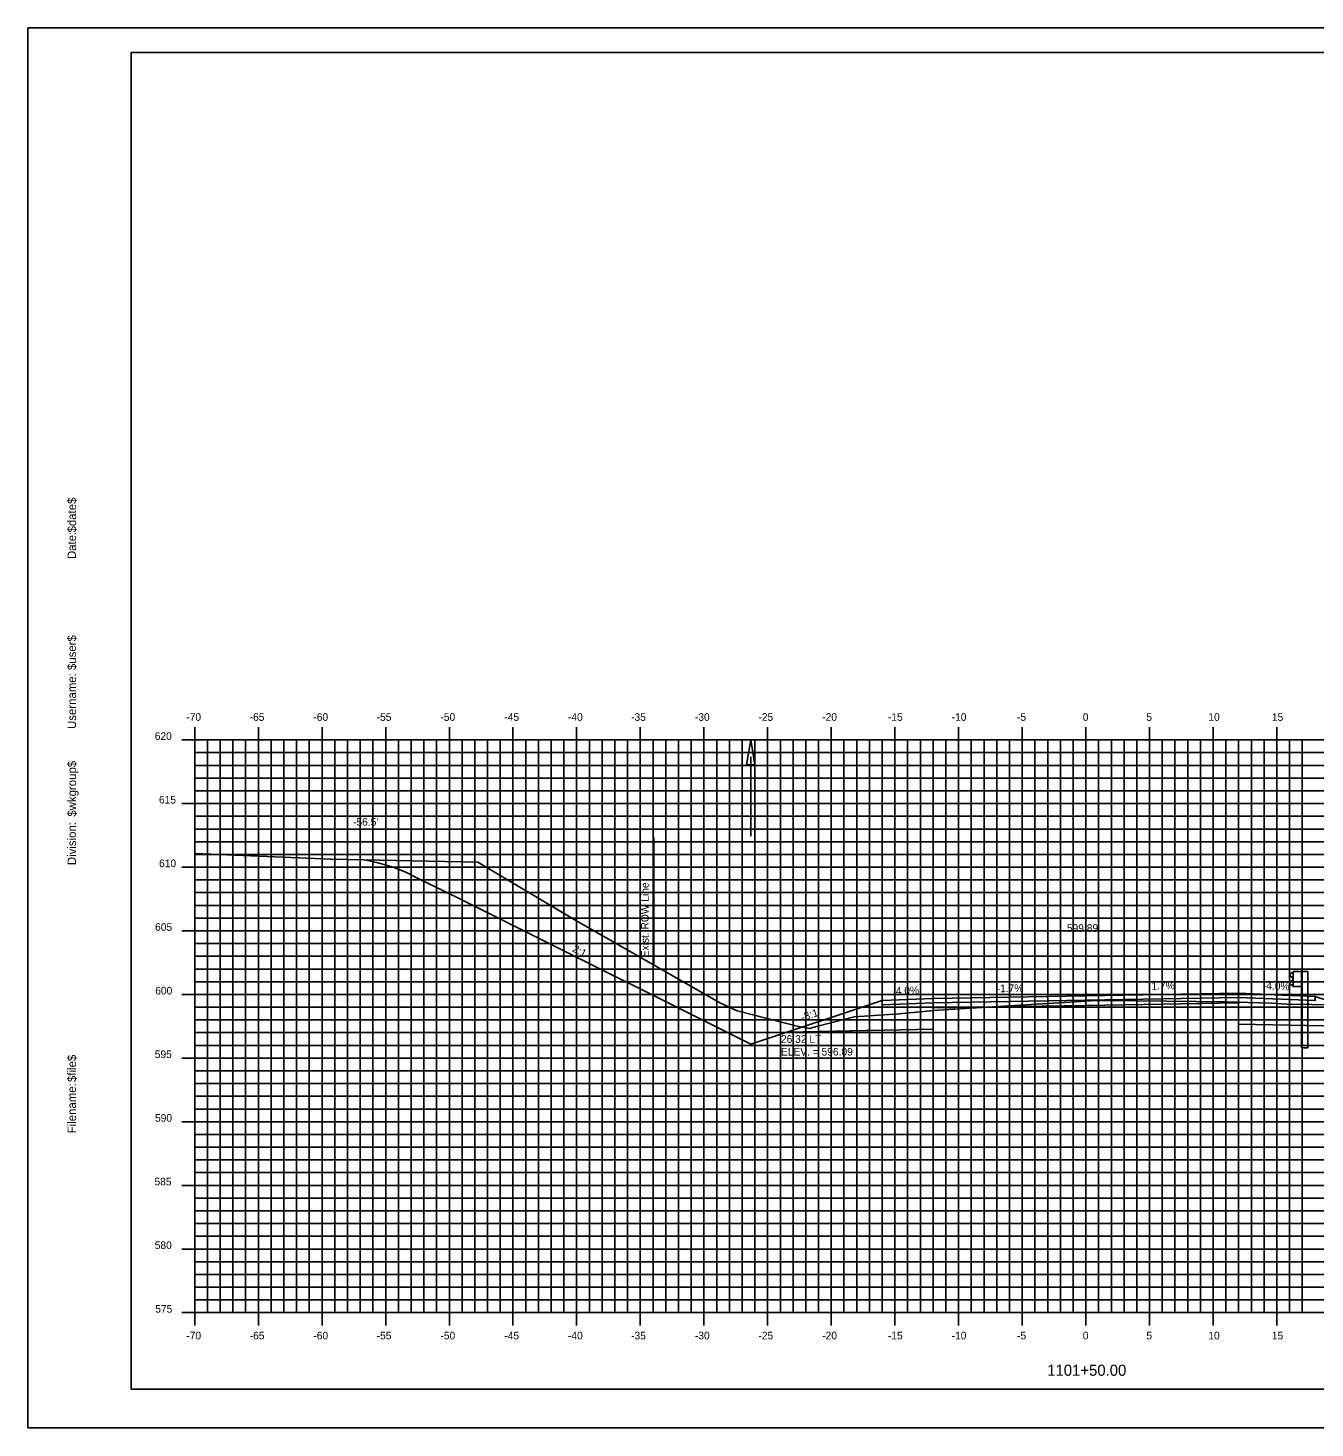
# Model space of a CAD drawing. Extents: x 1076747 to 1076917, y 779716 to 779826.
# Drawn here: x 1076747.2 to 1076848.3, y 779715.6 to 779825.6 of the extents above; entities that cross this region are included whole.
import ezdxf

# ---------------------------------------------------------------- set-up
doc = ezdxf.new("R2010")
doc.units = 0
for name, color, linetype in [('ANNOTATION', 7, 'Continuous'), ('BORDER', 7, 'Continuous'), ('D_Drainage_Culvert', 7, 'Continuous'), ('D_Drainage_Ditch_Line', 7, 'Continuous'), ('D_Guardrail_Beam_Rt', 7, 'Continuous'), ('D_Roadway_Centerline', 7, 'Continuous'), ('D_Roadway_Centerline_Text', 7, 'Continuous'), ('D_Roadway_Drive_SubGrade', 7, 'Continuous'), ('D_Roadway_Edge_Pavement', 7, 'Continuous'), ('D_Roadway_Edge_Shoulder', 7, 'Continuous'), ('D_Roadway_Pavement', 7, 'Continuous'), ('D_Roadway_SubGrade', 7, 'Continuous'), ('D_Text_Standard', 7, 'Continuous'), ('E_ROW_Line', 7, 'Continuous'), ('H_V ANNOTATION', 7, 'Continuous'), ('MAJOR', 7, 'Continuous'), ('MINOR', 7, 'Continuous'), ('PLOT BOUNDARY', 7, 'Continuous'), ('S_Roadway_Centerline', 7, 'Continuous')]:
    doc.layers.add(name, color=color, linetype=linetype)

msp = doc.modelspace()

# ---------------------------------------------------------------- linework, layer by layer
at = {"layer": 'BORDER'}
msp.add_lwpolyline([(1076755.31, 779718.71), (1076915.31, 779718.71), (1076915.31, 779823.71), (1076755.31, 779823.71)], close=True, dxfattribs=at)
at = {"layer": 'D_Drainage_Culvert'}
msp.add_line((1076814.31, 779746.9), (1076806.85, 779746.75), dxfattribs=at)
at = {"layer": 'D_Drainage_Ditch_Line'}
msp.add_line((1076803.98, 779768.39), (1076803.98, 779762.15), dxfattribs=at)
msp.add_lwpolyline([(1076804.31, 779767.74), (1076803.65, 779767.74), (1076803.98, 779769.71)], close=True, dxfattribs=at)
at = {"layer": 'D_Guardrail_Beam_Rt'}
for points in [[(1076846.59, 779751.51), (1076847.25, 779751.51), (1076847.25, 779750.33), (1076846.59, 779750.33)], [(1076847.25, 779751.51), (1076847.74, 779751.51), (1076847.74, 779745.51), (1076847.25, 779745.51)]]:
    msp.add_lwpolyline(points, close=True, dxfattribs=at)
msp.add_lwpolyline([(1076846.59, 779751.43), (1076846.5, 779751.42), (1076846.49, 779751.41), (1076846.34, 779751.31), (1076846.34, 779751.17), (1076846.54, 779751.03), (1076846.57, 779750.97), (1076846.57, 779750.88), (1076846.54, 779750.81), (1076846.34, 779750.68), (1076846.34, 779750.53), (1076846.49, 779750.43), (1076846.5, 779750.43), (1076846.59, 779750.41)], dxfattribs=at)
at = {"layer": 'D_Roadway_Centerline'}
msp.add_lwpolyline([(1076773.81, 779760.27), (1076774.81, 779760.02), (1076775.89, 779759.7), (1076776.89, 779759.31), (1076777.81, 779758.84), (1076781.14, 779757.22), (1076784.39, 779755.59)], dxfattribs=at)
at = {"layer": 'D_Roadway_Drive_SubGrade'}
msp.add_lwpolyline([(1076814.31, 779749.24), (1076803.98, 779745.8), (1076784.39, 779755.59)], dxfattribs=at)
at = {"layer": 'D_Roadway_Edge_Pavement'}
msp.add_lwpolyline([(1076818.31, 779749.06), (1076818.31, 779749.4), (1076830.31, 779749.6), (1076842.31, 779749.8), (1076842.31, 779749.47), (1076830.31, 779749.26)], close=True, dxfattribs=at)
at = {"layer": 'D_Roadway_Edge_Shoulder'}
msp.add_line((1076842.31, 779749.8), (1076848.31, 779749.56), dxfattribs=at)
msp.add_lwpolyline([(1076818.31, 779749.4), (1076814.31, 779749.24), (1076814.31, 779748.9), (1076818.31, 779749.06)], close=True, dxfattribs=at)
msp.add_lwpolyline([(1076842.31, 779749.8), (1076846.31, 779749.64), (1076846.31, 779749.64)], dxfattribs=at)
at = {"layer": 'D_Roadway_Pavement'}
msp.add_lwpolyline([(1076818.31, 779748.65), (1076818.31, 779749.06), (1076830.31, 779749.26), (1076842.31, 779749.47), (1076842.31, 779749.05), (1076830.31, 779748.85)], close=True, dxfattribs=at)
msp.add_lwpolyline([(1076818.31, 779749.06), (1076818.31, 779748.65)], dxfattribs=at)
msp.add_lwpolyline([(1076818.31, 779749.06), (1076818.31, 779748.65)], dxfattribs=at)
at = {"layer": 'D_Roadway_SubGrade'}
msp.add_lwpolyline([(1076842.31, 779747.38), (1076842.31, 779747.97), (1076842.31, 779749.47), (1076842.31, 779749.47), (1076848.31, 779749.23), (1076848.31, 779749.56), (1076855.64, 779747.12)], close=True, dxfattribs=at)
msp.add_lwpolyline([(1076806.85, 779746.75), (1076818.31, 779746.98), (1076818.31, 779749.06), (1076814.31, 779748.9), (1076814.31, 779749.24)], dxfattribs=at)
at = {"layer": 'E_ROW_Line'}
msp.add_line((1076796.37, 779752.03), (1076796.37, 779762.03), dxfattribs=at)
msp.add_line((1076796.37, 779752.03), (1076796.37, 779762.03), dxfattribs=at)
at = {"layer": 'MAJOR'}
for p, q in [((1076760.31, 779770.71), (1076760.31, 779769.71)), ((1076765.31, 779770.71), (1076765.31, 779769.71)), ((1076770.31, 779770.71), (1076770.31, 779769.71)), ((1076775.31, 779770.71), (1076775.31, 779769.71)), ((1076780.31, 779770.71), (1076780.31, 779769.71)), ((1076785.31, 779770.71), (1076785.31, 779769.71)), ((1076790.31, 779770.71), (1076790.31, 779769.71)), ((1076795.31, 779770.71), (1076795.31, 779769.71)), ((1076800.31, 779770.71), (1076800.31, 779769.71)), ((1076805.31, 779770.71), (1076805.31, 779769.71)), ((1076810.31, 779770.71), (1076810.31, 779769.71)), ((1076815.31, 779770.71), (1076815.31, 779769.71)), ((1076820.31, 779770.71), (1076820.31, 779769.71)), ((1076825.31, 779770.71), (1076825.31, 779769.71)), ((1076830.31, 779770.71), (1076830.31, 779769.71)), ((1076835.31, 779770.71), (1076835.31, 779769.71)), ((1076840.31, 779770.71), (1076840.31, 779769.71)), ((1076845.31, 779770.71), (1076845.31, 779769.71)), ((1076759.31, 779769.71), (1076760.31, 779769.71)), ((1076760.31, 779769.71), (1076900.31, 779769.71)), ((1076760.31, 779724.71), (1076760.31, 779769.71)), ((1076760.31, 779724.71), (1076760.31, 779769.71)), ((1076760.31, 779769.71), (1076900.31, 779769.71)), ((1076765.31, 779724.71), (1076765.31, 779769.71)), ((1076770.31, 779724.71), (1076770.31, 779769.71)), ((1076775.31, 779724.71), (1076775.31, 779769.71)), ((1076780.31, 779724.71), (1076780.31, 779769.71)), ((1076785.31, 779724.71), (1076785.31, 779769.71)), ((1076790.31, 779724.71), (1076790.31, 779769.71)), ((1076795.31, 779724.71), (1076795.31, 779769.71)), ((1076800.31, 779724.71), (1076800.31, 779769.71)), ((1076805.31, 779724.71), (1076805.31, 779769.71)), ((1076810.31, 779724.71), (1076810.31, 779769.71)), ((1076815.31, 779724.71), (1076815.31, 779769.71)), ((1076820.31, 779724.71), (1076820.31, 779769.71)), ((1076825.31, 779724.71), (1076825.31, 779769.71)), ((1076830.31, 779724.71), (1076830.31, 779769.71)), ((1076835.31, 779724.71), (1076835.31, 779769.71)), ((1076840.31, 779724.71), (1076840.31, 779769.71)), ((1076845.31, 779724.71), (1076845.31, 779769.71)), ((1076759.31, 779764.71), (1076760.31, 779764.71)), ((1076760.31, 779764.71), (1076900.31, 779764.71)), ((1076759.31, 779759.71), (1076760.31, 779759.71)), ((1076760.31, 779759.71), (1076900.31, 779759.71)), ((1076759.31, 779754.71), (1076760.31, 779754.71)), ((1076760.31, 779754.71), (1076900.31, 779754.71)), ((1076759.31, 779749.71), (1076760.31, 779749.71)), ((1076760.31, 779749.71), (1076900.31, 779749.71)), ((1076759.31, 779744.71), (1076760.31, 779744.71)), ((1076760.31, 779744.71), (1076900.31, 779744.71)), ((1076759.31, 779739.71), (1076760.31, 779739.71)), ((1076760.31, 779739.71), (1076900.31, 779739.71)), ((1076759.31, 779734.71), (1076760.31, 779734.71)), ((1076760.31, 779734.71), (1076900.31, 779734.71)), ((1076759.31, 779729.71), (1076760.31, 779729.71)), ((1076760.31, 779729.71), (1076900.31, 779729.71)), ((1076759.31, 779724.71), (1076760.31, 779724.71)), ((1076760.31, 779724.71), (1076900.31, 779724.71)), ((1076760.31, 779724.71), (1076900.31, 779724.71)), ((1076760.31, 779723.7), (1076760.31, 779724.71)), ((1076765.31, 779723.7), (1076765.31, 779724.71)), ((1076770.31, 779723.7), (1076770.31, 779724.71)), ((1076775.31, 779723.7), (1076775.31, 779724.71)), ((1076780.31, 779723.7), (1076780.31, 779724.71)), ((1076785.31, 779723.7), (1076785.31, 779724.71)), ((1076790.31, 779723.7), (1076790.31, 779724.71)), ((1076795.31, 779723.7), (1076795.31, 779724.71)), ((1076800.31, 779723.7), (1076800.31, 779724.71)), ((1076805.31, 779723.7), (1076805.31, 779724.71)), ((1076810.31, 779723.7), (1076810.31, 779724.71)), ((1076815.31, 779723.7), (1076815.31, 779724.71)), ((1076820.31, 779723.7), (1076820.31, 779724.71)), ((1076825.31, 779723.7), (1076825.31, 779724.71)), ((1076830.31, 779723.7), (1076830.31, 779724.71)), ((1076835.31, 779723.7), (1076835.31, 779724.71)), ((1076840.31, 779723.7), (1076840.31, 779724.71)), ((1076845.31, 779723.7), (1076845.31, 779724.71))]:
    msp.add_line(p, q, dxfattribs=at)
at = {"layer": 'MINOR'}
for p, q in [((1076761.31, 779724.71), (1076761.31, 779769.71)), ((1076762.31, 779724.71), (1076762.31, 779769.71)), ((1076763.31, 779724.71), (1076763.31, 779769.71)), ((1076764.31, 779724.71), (1076764.31, 779769.71)), ((1076766.31, 779724.71), (1076766.31, 779769.71)), ((1076767.31, 779724.71), (1076767.31, 779769.71)), ((1076768.31, 779724.71), (1076768.31, 779769.71)), ((1076769.31, 779724.71), (1076769.31, 779769.71)), ((1076771.31, 779724.71), (1076771.31, 779769.71)), ((1076772.31, 779724.71), (1076772.31, 779769.71)), ((1076773.31, 779724.71), (1076773.31, 779769.71)), ((1076774.31, 779724.71), (1076774.31, 779769.71)), ((1076776.31, 779724.71), (1076776.31, 779769.71)), ((1076777.31, 779724.71), (1076777.31, 779769.71)), ((1076778.31, 779724.71), (1076778.31, 779769.71)), ((1076779.31, 779724.71), (1076779.31, 779769.71)), ((1076781.31, 779724.71), (1076781.31, 779769.71)), ((1076782.31, 779724.71), (1076782.31, 779769.71)), ((1076783.31, 779724.71), (1076783.31, 779769.71)), ((1076784.31, 779724.71), (1076784.31, 779769.71)), ((1076786.31, 779724.71), (1076786.31, 779769.71)), ((1076787.31, 779724.71), (1076787.31, 779769.71)), ((1076788.31, 779724.71), (1076788.31, 779769.71)), ((1076789.31, 779724.71), (1076789.31, 779769.71)), ((1076791.31, 779724.71), (1076791.31, 779769.71)), ((1076792.31, 779724.71), (1076792.31, 779769.71)), ((1076793.31, 779724.71), (1076793.31, 779769.71)), ((1076794.31, 779724.71), (1076794.31, 779769.71)), ((1076796.31, 779724.71), (1076796.31, 779769.71)), ((1076797.31, 779724.71), (1076797.31, 779769.71)), ((1076798.31, 779724.71), (1076798.31, 779769.71)), ((1076799.31, 779724.71), (1076799.31, 779769.71)), ((1076801.31, 779724.71), (1076801.31, 779769.71)), ((1076802.31, 779724.71), (1076802.31, 779769.71)), ((1076803.31, 779724.71), (1076803.31, 779769.71)), ((1076804.31, 779724.71), (1076804.31, 779769.71)), ((1076806.31, 779724.71), (1076806.31, 779769.71)), ((1076807.31, 779724.71), (1076807.31, 779769.71)), ((1076808.31, 779724.71), (1076808.31, 779769.71)), ((1076809.31, 779724.71), (1076809.31, 779769.71)), ((1076811.31, 779724.71), (1076811.31, 779769.71)), ((1076812.31, 779724.71), (1076812.31, 779769.71)), ((1076813.31, 779724.71), (1076813.31, 779769.71)), ((1076814.31, 779724.71), (1076814.31, 779769.71)), ((1076816.31, 779724.71), (1076816.31, 779769.71)), ((1076817.31, 779724.71), (1076817.31, 779769.71)), ((1076818.31, 779724.71), (1076818.31, 779769.71)), ((1076819.31, 779724.71), (1076819.31, 779769.71)), ((1076821.31, 779724.71), (1076821.31, 779769.71)), ((1076822.31, 779724.71), (1076822.31, 779769.71)), ((1076823.31, 779724.71), (1076823.31, 779769.71)), ((1076824.31, 779724.71), (1076824.31, 779769.71)), ((1076826.31, 779724.71), (1076826.31, 779769.71)), ((1076827.31, 779724.71), (1076827.31, 779769.71)), ((1076828.31, 779724.71), (1076828.31, 779769.71)), ((1076829.31, 779724.71), (1076829.31, 779769.71)), ((1076831.31, 779724.71), (1076831.31, 779769.71)), ((1076832.31, 779724.71), (1076832.31, 779769.71)), ((1076833.31, 779724.71), (1076833.31, 779769.71)), ((1076834.31, 779724.71), (1076834.31, 779769.71)), ((1076836.31, 779724.71), (1076836.31, 779769.71)), ((1076837.31, 779724.71), (1076837.31, 779769.71)), ((1076838.31, 779724.71), (1076838.31, 779769.71)), ((1076839.31, 779724.71), (1076839.31, 779769.71)), ((1076841.31, 779724.71), (1076841.31, 779769.71)), ((1076842.31, 779724.71), (1076842.31, 779769.71)), ((1076843.31, 779724.71), (1076843.31, 779769.71)), ((1076844.31, 779724.71), (1076844.31, 779769.71)), ((1076846.31, 779724.71), (1076846.31, 779769.71)), ((1076847.31, 779724.71), (1076847.31, 779769.71)), ((1076760.31, 779768.71), (1076900.31, 779768.71)), ((1076760.31, 779768.71), (1076761.31, 779768.71)), ((1076760.31, 779767.71), (1076900.31, 779767.71)), ((1076760.31, 779767.71), (1076761.31, 779767.71)), ((1076760.31, 779766.71), (1076900.31, 779766.71)), ((1076760.31, 779766.71), (1076761.31, 779766.71)), ((1076760.31, 779765.71), (1076900.31, 779765.71)), ((1076760.31, 779765.71), (1076761.31, 779765.71)), ((1076760.31, 779763.71), (1076900.31, 779763.71)), ((1076760.31, 779763.71), (1076761.31, 779763.71)), ((1076760.31, 779762.71), (1076900.31, 779762.71)), ((1076760.31, 779762.71), (1076761.31, 779762.71)), ((1076760.31, 779761.71), (1076900.31, 779761.71)), ((1076760.31, 779761.71), (1076761.31, 779761.71)), ((1076760.31, 779760.71), (1076900.31, 779760.71)), ((1076760.31, 779760.71), (1076761.31, 779760.71)), ((1076760.31, 779758.71), (1076900.31, 779758.71)), ((1076760.31, 779758.71), (1076761.31, 779758.71)), ((1076760.31, 779757.71), (1076900.31, 779757.71)), ((1076760.31, 779757.71), (1076761.31, 779757.71)), ((1076760.31, 779756.71), (1076900.31, 779756.71)), ((1076760.31, 779756.71), (1076761.31, 779756.71)), ((1076760.31, 779755.71), (1076900.31, 779755.71)), ((1076760.31, 779755.71), (1076761.31, 779755.71)), ((1076760.31, 779753.71), (1076900.31, 779753.71)), ((1076760.31, 779753.71), (1076761.31, 779753.71)), ((1076760.31, 779752.71), (1076900.31, 779752.71)), ((1076760.31, 779752.71), (1076761.31, 779752.71)), ((1076760.31, 779751.71), (1076900.31, 779751.71)), ((1076760.31, 779751.71), (1076761.31, 779751.71)), ((1076760.31, 779750.71), (1076900.31, 779750.71)), ((1076760.31, 779750.71), (1076761.31, 779750.71)), ((1076760.31, 779748.71), (1076900.31, 779748.71)), ((1076760.31, 779748.71), (1076761.31, 779748.71)), ((1076760.31, 779747.71), (1076900.31, 779747.71)), ((1076760.31, 779747.71), (1076761.31, 779747.71)), ((1076760.31, 779746.71), (1076900.31, 779746.71)), ((1076760.31, 779746.71), (1076761.31, 779746.71)), ((1076760.31, 779745.71), (1076900.31, 779745.71)), ((1076760.31, 779745.71), (1076761.31, 779745.71)), ((1076760.31, 779743.71), (1076900.31, 779743.71)), ((1076760.31, 779743.71), (1076761.31, 779743.71)), ((1076760.31, 779742.71), (1076900.31, 779742.71)), ((1076760.31, 779742.71), (1076761.31, 779742.71)), ((1076760.31, 779741.71), (1076900.31, 779741.71)), ((1076760.31, 779741.71), (1076761.31, 779741.71)), ((1076760.31, 779740.71), (1076900.31, 779740.71)), ((1076760.31, 779740.71), (1076761.31, 779740.71)), ((1076760.31, 779738.71), (1076900.31, 779738.71)), ((1076760.31, 779738.71), (1076761.31, 779738.71)), ((1076760.31, 779737.71), (1076900.31, 779737.71)), ((1076760.31, 779737.71), (1076761.31, 779737.71)), ((1076760.31, 779736.71), (1076900.31, 779736.71)), ((1076760.31, 779736.71), (1076761.31, 779736.71)), ((1076760.31, 779735.71), (1076900.31, 779735.71)), ((1076760.31, 779735.71), (1076761.31, 779735.71)), ((1076760.31, 779733.71), (1076900.31, 779733.71)), ((1076760.31, 779733.71), (1076761.31, 779733.71)), ((1076760.31, 779732.71), (1076900.31, 779732.71)), ((1076760.31, 779732.71), (1076761.31, 779732.71)), ((1076760.31, 779731.71), (1076900.31, 779731.71)), ((1076760.31, 779731.71), (1076761.31, 779731.71)), ((1076760.31, 779730.71), (1076900.31, 779730.71)), ((1076760.31, 779730.71), (1076761.31, 779730.71)), ((1076760.31, 779728.71), (1076900.31, 779728.71)), ((1076760.31, 779728.71), (1076761.31, 779728.71)), ((1076760.31, 779727.71), (1076900.31, 779727.71)), ((1076760.31, 779727.71), (1076761.31, 779727.71)), ((1076760.31, 779726.71), (1076900.31, 779726.71)), ((1076760.31, 779726.71), (1076761.31, 779726.71)), ((1076760.31, 779725.71), (1076900.31, 779725.71)), ((1076760.31, 779725.71), (1076761.31, 779725.71))]:
    msp.add_line(p, q, dxfattribs=at)
at = {"layer": 'PLOT BOUNDARY'}
msp.add_lwpolyline([(1076747.21, 779715.65), (1076917.21, 779715.65), (1076917.21, 779825.65), (1076747.21, 779825.65)], close=True, dxfattribs=at)
at = {"layer": 'S_Roadway_Centerline'}
msp.add_lwpolyline([(1076760.31, 779760.79), (1076770.99, 779760.33), (1076782.56, 779760.11), (1076790.11, 779755.6), (1076801.62, 779749.03), (1076802.91, 779748.43), (1076804.35, 779748.05), (1076807.74, 779747.19), (1076808.6, 779747.03), (1076809.25, 779747.21), (1076812.11, 779747.94), (1076815.62, 779748.18), (1076818.68, 779748.47), (1076830.35, 779749.18), (1076830.94, 779749.23), (1076832.05, 779749.23), (1076841.27, 779749.14), (1076844.85, 779749.02), (1076846.55, 779748.91), (1076847, 779748.94), (1076849.09, 779748.9)], dxfattribs=at)

# ---------------------------------------------------------------- texts
at = {"layer": 'ANNOTATION'}
for s, rotation, p in [('2:1', 333.4349, (1076789.91, 779753.11)), ('-1.7%', 0.9596, (1076823.31, 779749.88)), ('1.7%', 0.9596, (1076835.47, 779750.08)), ('-4.0%', 357.7094, (1076844.2, 779750.12)), ('-4.0%', 2.2906, (1076815.12, 779749.67)), ('-3:1', 18.4349, (1076808.03, 779747.6))]:
    msp.add_text(s, height=0.6, rotation=rotation, dxfattribs=at).set_placement(p)
for s, p in [('26.32 LT', (1076806.36, 779745.91)), ('ELEV. = 596.09', (1076806.36, 779744.91))]:
    msp.add_text(s, height=0.6, dxfattribs=at).set_placement(p)
at = {"layer": 'BORDER'}
for s, p in [('$date$', (1076750.99, 779786.01)), ('Date:', (1076750.99, 779783.92)), ('$user$', (1076750.99, 779775.2)), ('Username:', (1076750.99, 779770.57)), ('$wkgroup$', (1076750.99, 779763.68)), ('Division:', (1076750.99, 779759.87)), ('$file$', (1076750.99, 779742.83)), ('Filename:', (1076750.99, 779738.8))]:
    msp.add_text(s, height=0.67, rotation=90, dxfattribs=at).set_placement(p)
at = {"layer": 'D_Roadway_Centerline_Text'}
msp.add_text('599.89', height=0.6, dxfattribs=at).set_placement((1076828.82, 779754.63))
at = {"layer": 'D_Text_Standard'}
msp.add_text("-56.5'", height=0.6, dxfattribs=at).set_placement((1076772.75, 779762.97))
at = {"layer": 'E_ROW_Line'}
msp.add_text('Exist. ROW Line', height=0.6, rotation=90, dxfattribs=at).set_placement((1076795.97, 779752.63))
at = {"layer": 'H_V ANNOTATION'}
for s, height, p in [('-70', 0.6, (1076759.65, 779771.21)), ('-65', 0.6, (1076764.63, 779771.21)), ('-60', 0.6, (1076769.63, 779771.21)), ('-55', 0.6, (1076774.6, 779771.21)), ('-50', 0.6, (1076779.61, 779771.21)), ('-45', 0.6, (1076784.63, 779771.21)), ('-40', 0.6, (1076789.63, 779771.21)), ('-35', 0.6, (1076794.59, 779771.21)), ('-30', 0.6, (1076799.6, 779771.21)), ('-25', 0.6, (1076804.59, 779771.21)), ('-20', 0.6, (1076809.6, 779771.21)), ('-15', 0.6, (1076814.76, 779771.21)), ('-10', 0.6, (1076819.77, 779771.21)), ('-5', 0.6, (1076824.9, 779771.21)), ('0', 0.6, (1076830.07, 779771.21)), ('5', 0.6, (1076835.06, 779771.21)), ('10', 0.6, (1076839.93, 779771.21)), ('15', 0.6, (1076844.92, 779771.21)), ('620', 0.6, (1076757.17, 779769.71)), ('615', 0.6, (1076757.5, 779764.71)), ('610', 0.6, (1076757.51, 779759.71)), ('605', 0.6, (1076757.2, 779754.71)), ('600', 0.6, (1076757.21, 779749.71)), ('595', 0.6, (1076757.17, 779744.71)), ('590', 0.6, (1076757.19, 779739.71)), ('585', 0.6, (1076757.15, 779734.71)), ('580', 0.6, (1076757.17, 779729.71)), ('575', 0.6, (1076757.21, 779724.71)), ('-70', 0.6, (1076759.65, 779722.61)), ('-65', 0.6, (1076764.63, 779722.61)), ('-60', 0.6, (1076769.63, 779722.61)), ('-55', 0.6, (1076774.6, 779722.61)), ('-50', 0.6, (1076779.61, 779722.61)), ('-45', 0.6, (1076784.63, 779722.61)), ('-40', 0.6, (1076789.63, 779722.61)), ('-35', 0.6, (1076794.59, 779722.61)), ('-30', 0.6, (1076799.6, 779722.61)), ('-25', 0.6, (1076804.59, 779722.61)), ('-20', 0.6, (1076809.6, 779722.61)), ('-15', 0.6, (1076814.76, 779722.61)), ('-10', 0.6, (1076819.77, 779722.61)), ('-5', 0.6, (1076824.9, 779722.61)), ('0', 0.6, (1076830.07, 779722.61)), ('5', 0.6, (1076835.06, 779722.61)), ('10', 0.6, (1076839.93, 779722.61)), ('15', 0.6, (1076844.92, 779722.61)), ('1101+50.00', 0.875, (1076827.27, 779719.75))]:
    msp.add_text(s, height=height, dxfattribs=at).set_placement(p)
at = {"layer": 'MAJOR'}
msp.add_text('-', height=0.006, dxfattribs=at).set_placement((1076760.3, 779724.71))

doc.saveas('drawing.dxf')
